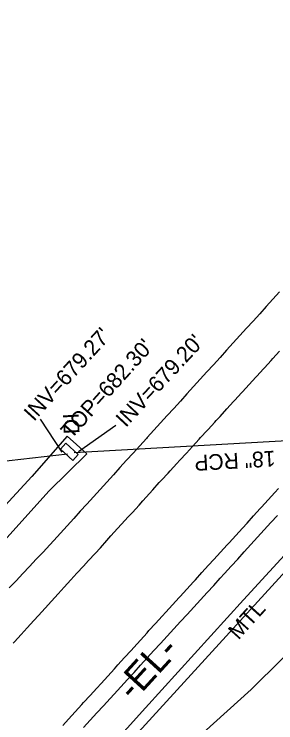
# Model space of a CAD drawing. Extents: x 1806071 to 1809844, y 912722 to 917035.
# Drawn here: x 1807680.7 to 1807747.2, y 914525.2 to 914705.5 of the extents above; entities that cross this region are included whole.
import ezdxf

# ---------------------------------------------------------------- set-up
doc = ezdxf.new("R2010")
doc.units = 0
for name, color, linetype in [('Exist Guardrail', 7, 'Continuous'), ('Exist Guardrail Text', 7, 'Continuous'), ('Exist Horizontal Alignment', 7, 'Continuous'), ('Exist Horizontal Alignment Direction Label', 7, 'Continuous'), ('Exist Roads EOP', 7, 'Continuous'), ('Exist Roads EOT', 7, 'Continuous'), ('Exist Structure Minor Drop Inlet', 7, 'Continuous'), ('Exist Structure Minor Drop Inlet Text', 7, 'Continuous'), ('Exist Structure Minor Drop Inlet Top Elevation', 7, 'Continuous'), ('Exist Structure Minor Paved Ditch or Gutter', 7, 'Continuous'), ('Exist Structure Minor Pipes RCP 18 Inch', 7, 'Continuous'), ('Exist Structure Minor Pipes RCP 18 Inch Invert', 7, 'Continuous'), ('Exist Structure Minor Pipes RCP 18 Inch Text', 7, 'Continuous')]:
    doc.layers.add(name, color=color, linetype=linetype)

msp = doc.modelspace()

# ---------------------------------------------------------------- linework, layer by layer
at = {"layer": 'Exist Guardrail'}
for points in [[(1807963.2, 914783.22), (1807935.17, 914760.04), (1807908.57, 914736.42), (1807882.27, 914710.65), (1807863.47, 914692.52), (1807840.66, 914668.07), (1807814.87, 914639.07), (1807789.47, 914611.6), (1807764.43, 914584.29), (1807738.95, 914556.51), (1807714.06, 914529.04), (1807691.49, 914504.04)], [(1807680.51, 914480.34), (1807706.97, 914502.99), (1807740.87, 914533.67), (1807772.15, 914564.62), (1807800.61, 914594.77), (1807854.85, 914654.76), (1807877.02, 914678.62), (1807893.92, 914697.43), (1807918.63, 914724.67), (1807943.49, 914751.73), (1807951.56, 914760.68)]]:
    msp.add_lwpolyline(points, dxfattribs=at)
at = {"layer": 'Exist Horizontal Alignment'}
msp.add_line((1806073.69, 912724.84), (1809374.2, 916346.52), dxfattribs=at)
at = {"layer": 'Exist Roads EOP'}
for points in [[(1807748.12, 914634.81), (1807746.44, 914632.96), (1807744.76, 914631.11), (1807743.08, 914629.26), (1807741.4, 914627.41), (1807739.72, 914625.56), (1807738.04, 914623.71), (1807736.36, 914621.85), (1807734.68, 914620), (1807733, 914618.15), (1807731.32, 914616.3), (1807729.64, 914614.45), (1807727.96, 914612.6), (1807726.28, 914610.75), (1807724.6, 914608.89), (1807722.92, 914607.04), (1807721.24, 914605.19), (1807719.56, 914603.34), (1807717.88, 914601.49), (1807716.2, 914599.64), (1807714.52, 914597.79), (1807714.29, 914597.53), (1807712.61, 914595.68), (1807710.93, 914593.83), (1807709.25, 914591.98), (1807707.57, 914590.13), (1807705.89, 914588.28), (1807704.21, 914586.43), (1807702.53, 914584.57), (1807700.85, 914582.72), (1807699.17, 914580.87), (1807697.49, 914579.02), (1807695.81, 914577.17), (1807694.13, 914575.32), (1807692.45, 914573.47), (1807690.77, 914571.62), (1807689.73, 914570.47), (1807688.01, 914568.65), (1807686.3, 914566.83), (1807684.59, 914565.01), (1807682.87, 914563.19), (1807681.16, 914561.37), (1807679.45, 914559.55)], [(1807698.33, 914524.04), (1807700.02, 914525.89), (1807701.7, 914527.73), (1807703.39, 914529.58), (1807705.08, 914531.42), (1807706.07, 914532.51), (1807707.76, 914534.35), (1807709.45, 914536.2), (1807711.14, 914538.04), (1807712.82, 914539.89), (1807714.51, 914541.73), (1807716.2, 914543.58), (1807717.89, 914545.42), (1807719.57, 914547.26), (1807721.26, 914549.11), (1807722.95, 914550.95), (1807724.64, 914552.8), (1807726.32, 914554.64), (1807728.01, 914556.49), (1807729.7, 914558.33), (1807731.39, 914560.18), (1807733.07, 914562.02), (1807734.13, 914563.17), (1807735.8, 914565.03), (1807737.48, 914566.88), (1807739.16, 914568.73), (1807740.84, 914570.58), (1807742.52, 914572.43), (1807744.2, 914574.29), (1807745.88, 914576.14), (1807747.56, 914577.99)]]:
    msp.add_lwpolyline(points, dxfattribs=at)
at = {"layer": 'Exist Roads EOT'}
for points in [[(1807680.44, 914545.44), (1807680.8, 914545.83), (1807682.48, 914547.68), (1807684.01, 914549.37), (1807685.7, 914551.22), (1807686.88, 914552.52), (1807688.56, 914554.37), (1807690.2, 914556.18), (1807691.89, 914558.02), (1807693.42, 914559.69), (1807695.09, 914561.55), (1807696.63, 914563.25), (1807698.32, 914565.1), (1807699.58, 914566.48), (1807701.28, 914568.32), (1807702.61, 914569.75), (1807704.27, 914571.63), (1807705.28, 914572.77), (1807706.97, 914574.62), (1807707.99, 914575.75), (1807709.68, 914577.59), (1807710.75, 914578.75), (1807712.41, 914580.61), (1807713.4, 914581.72), (1807715.09, 914583.57), (1807715.89, 914584.44), (1807717.56, 914586.3), (1807718.1, 914586.9), (1807719.79, 914588.74), (1807720.33, 914589.32), (1807722.03, 914591.16), (1807722.79, 914591.99), (1807724.47, 914593.84), (1807725.99, 914595.53), (1807727.69, 914597.36), (1807728.04, 914597.75), (1807729.75, 914599.58), (1807729.96, 914599.8), (1807731.64, 914601.65), (1807732.04, 914602.1), (1807733, 914603.17), (1807734.74, 914605.06), (1807736.42, 914606.91), (1807736.75, 914607.27), (1807738.44, 914609.11), (1807738.74, 914609.44), (1807740.42, 914611.28), (1807742.1, 914613.13), (1807742.33, 914613.38), (1807744.02, 914615.22), (1807744.3, 914615.52), (1807745.98, 914617.37), (1807746.44, 914617.88), (1807748.13, 914619.72)], [(1807693.03, 914524.5), (1807694.52, 914526.13), (1807696.2, 914527.99), (1807697.87, 914529.85), (1807698.32, 914530.35), (1807700, 914532.2), (1807701.68, 914534.05), (1807702.78, 914535.26), (1807704.47, 914537.11), (1807706.15, 914538.95), (1807707.06, 914539.94), (1807708.74, 914541.8), (1807710.42, 914543.65), (1807711.1, 914544.4), (1807712.77, 914546.25), (1807714.44, 914548.11), (1807714.93, 914548.66), (1807716.61, 914550.51), (1807718.29, 914552.36), (1807719.22, 914553.38), (1807720.9, 914555.23), (1807722.59, 914557.08), (1807722.85, 914557.37), (1807724.54, 914559.21), (1807726.23, 914561.05), (1807726.72, 914561.59), (1807728.41, 914563.43), (1807730.09, 914565.28), (1807731.46, 914566.77), (1807733.15, 914568.62), (1807734.83, 914570.47), (1807735.33, 914571.02), (1807737.02, 914572.86), (1807738.71, 914574.7), (1807739.87, 914575.96), (1807741.53, 914577.83), (1807743.19, 914579.7), (1807743.53, 914580.08), (1807745.23, 914581.92), (1807746.92, 914583.76), (1807747.88, 914584.8)], [(1807693.03, 914524.5), (1807694.52, 914526.13), (1807696.2, 914527.99), (1807697.87, 914529.85), (1807698.32, 914530.35), (1807700, 914532.2), (1807701.68, 914534.05), (1807702.78, 914535.26), (1807704.47, 914537.11), (1807706.15, 914538.95), (1807707.06, 914539.94), (1807708.74, 914541.8), (1807710.42, 914543.65), (1807711.1, 914544.4), (1807712.77, 914546.25), (1807714.44, 914548.11), (1807714.93, 914548.66), (1807716.61, 914550.51), (1807718.29, 914552.36), (1807719.22, 914553.38), (1807720.9, 914555.23), (1807722.59, 914557.08), (1807722.85, 914557.37), (1807724.54, 914559.21), (1807726.23, 914561.05), (1807726.72, 914561.59), (1807728.41, 914563.43), (1807730.09, 914565.28), (1807731.46, 914566.77), (1807733.15, 914568.62), (1807734.83, 914570.47), (1807735.33, 914571.02), (1807737.02, 914572.86), (1807738.71, 914574.7), (1807739.87, 914575.96), (1807741.53, 914577.83), (1807743.19, 914579.7), (1807743.53, 914580.08), (1807745.23, 914581.92), (1807746.92, 914583.76), (1807747.88, 914584.8)]]:
    msp.add_lwpolyline(points, dxfattribs=at)
at = {"layer": 'Exist Structure Minor Drop Inlet'}
msp.add_lwpolyline([(1807693.81, 914596.31), (1807696.97, 914593.49), (1807695.59, 914591.96), (1807692.44, 914594.78)], close=True, dxfattribs=at)
at = {"layer": 'Exist Structure Minor Paved Ditch or Gutter'}
msp.add_lwpolyline([(1807694.13, 914598.14), (1807685.14, 914587.9), (1807661.82, 914562.55), (1807636, 914533.24), (1807610.54, 914505.15), (1807588.79, 914481.21), (1807590.5, 914479.46), (1807592.71, 914477.21), (1807614.46, 914500.9), (1807640.09, 914529.28), (1807666.56, 914558.68), (1807689.56, 914584.2), (1807699.17, 914593.67), (1807696.54, 914596.01), (1807694.13, 914598.14)], dxfattribs=at)
at = {"layer": 'Exist Structure Minor Pipes RCP 18 Inch'}
for p, q in [((1807792.71, 914599.43), (1807695.95, 914593.87)), ((1807694.22, 914593.59), (1807612.91, 914584.14))]:
    msp.add_line(p, q, dxfattribs=at)
at = {"layer": 'Exist Structure Minor Pipes RCP 18 Inch Invert'}
for p, q in [((1807692.91, 914594.09), (1807687.36, 914602.49)), ((1807697.04, 914594.24), (1807706.48, 914600.93))]:
    msp.add_line(p, q, dxfattribs=at)

# ---------------------------------------------------------------- texts
at = {"layer": 'Exist Guardrail Text'}
msp.add_text('MTL', height=4, rotation=47.8108, dxfattribs=at).set_placement((1807737.66, 914546.15))
at = {"layer": 'Exist Horizontal Alignment Direction Label'}
msp.add_text('-EL-', height=7, rotation=47.6564, dxfattribs=at).set_placement((1807711.03, 914530.42))
at = {"layer": 'Exist Structure Minor Drop Inlet Text'}
msp.add_text('DI', height=4, rotation=92.8422, dxfattribs=at).set_placement((1807697.31, 914598.75))
at = {"layer": 'Exist Structure Minor Drop Inlet Top Elevation'}
msp.add_text("TOP=682.30'", height=4, rotation=47.9615, dxfattribs=at).set_placement((1807695.16, 914597.21))
at = {"layer": 'Exist Structure Minor Pipes RCP 18 Inch Invert'}
for s, rotation, p in [("INV=679.27'", 47.6306, (1807685.71, 914601.69)), ("INV=679.20'", 47.0712, (1807709.05, 914600.16))]:
    msp.add_text(s, height=4, rotation=rotation, dxfattribs=at).set_placement(p)
at = {"layer": 'Exist Structure Minor Pipes RCP 18 Inch Text'}
msp.add_text('18" RCP', height=4, rotation=183.2851, dxfattribs=at).set_placement((1807746.97, 914594.45))

doc.saveas('drawing.dxf')
